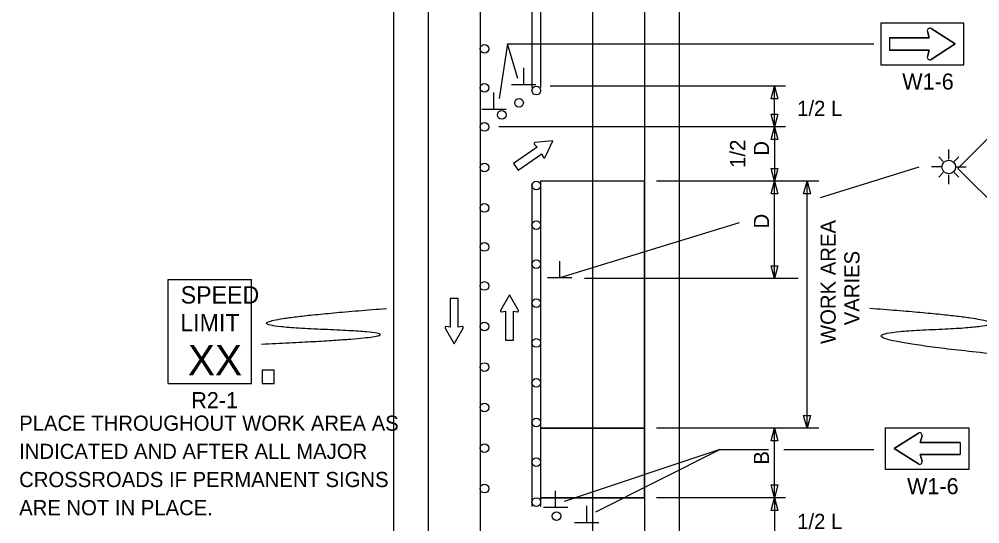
# Model space of a CAD drawing. Extents: x 16731 to 18475, y 7218 to 8213.
# Drawn here: x 16732.4 to 17176, y 7711.7 to 7944.5 of the extents above; entities that cross this region are included whole.
import ezdxf

# ---------------------------------------------------------------- set-up
doc = ezdxf.new("R2010")
doc.units = 0
for name, color, linetype in [('ALI_LEGAL_EX', 7, 'Continuous'), ('MT_SCRATCH_LEVEL_A', 7, 'Continuous'), ('MT_SCRATCH_LEVEL_E', 7, 'Continuous'), ('PAVT_EDGE_EX', 7, 'Continuous'), ('TRAFFIC_SIGNS_PR', 7, 'Continuous'), ('TYPICAL_TEXT_DIMEN_PR', 7, 'Continuous')]:
    doc.layers.add(name, color=color, linetype=linetype)

msp = doc.modelspace()

# ---------------------------------------------------------------- linework, layer by layer
at = {"layer": 'ALI_LEGAL_EX'}
for p, q in [((16945.19, 8201.12), (16945.19, 7350.01)), ((16997.19, 8201.12), (16997.19, 7350.01))]:
    msp.add_line(p, q, dxfattribs=at)
for points in [[(16945.19, 7901.12), (16945.19, 7876.12)], [(16997.19, 7891.94), (16997.19, 7876.12)], [(16945.19, 7801.12), (16945.19, 7776.12)], [(16997.19, 7801.12), (16997.19, 7776.12)]]:
    msp.add_lwpolyline(points, dxfattribs=at)
at = {"layer": 'MT_SCRATCH_LEVEL_A'}
for p, q in [((17021.19, 7869.79), (16973.19, 7869.79)), ((17021.19, 7869.79), (16973.19, 7869.79)), ((16973.19, 7869.79), (16973.19, 7755.78)), ((16973.19, 7869.11), (16973.19, 7723.73)), ((17021.19, 7755.78), (17021.19, 7869.79)), ((17021.19, 7833.79), (17021.19, 7723.73)), ((17021.19, 7755.78), (16973.19, 7755.78)), ((16973.19, 7755.78), (17021.19, 7755.78)), ((17021.19, 7755.78), (16973.19, 7755.78)), ((16973.19, 7755.78), (16973.19, 7723.73)), ((17021.19, 7723.73), (17021.19, 7755.78)), ((17021.19, 7723.73), (16973.19, 7723.73)), ((16973.19, 7723.73), (17021.19, 7723.73))]:
    msp.add_line(p, q, dxfattribs=at)
at = {"layer": 'MT_SCRATCH_LEVEL_E'}
for p, q in [((16970.25, 7886.78), (16971.52, 7885.5)), ((16970.25, 7886.78), (16971.52, 7885.5)), ((16978.82, 7888.34), (16970.53, 7887.57)), ((16978.82, 7888.34), (16970.53, 7887.57)), ((16975.26, 7880.8), (16978.82, 7888.34)), ((16975.26, 7880.8), (16978.82, 7888.34)), ((16971.52, 7885.5), (16960.65, 7877.91)), ((16971.52, 7885.5), (16960.65, 7877.91)), ((16962.8, 7874.85), (16973.67, 7882.44)), ((16962.8, 7874.85), (16973.67, 7882.44)), ((16973.67, 7882.44), (16974.42, 7880.8)), ((16973.67, 7882.44), (16974.42, 7880.8)), ((16960.65, 7877.91), (16962.8, 7874.85)), ((16960.65, 7877.91), (16962.8, 7874.85)), ((16958.8, 7817.35), (16954.69, 7810.11)), ((16958.8, 7817.35), (16954.69, 7810.11)), ((16962.95, 7810.11), (16958.8, 7817.35)), ((16962.95, 7810.11), (16958.8, 7817.35)), ((16935.11, 7815.63), (16931.37, 7815.63)), ((16931.37, 7815.63), (16931.37, 7802.38)), ((16935.11, 7815.63), (16931.37, 7815.63)), ((16931.37, 7815.63), (16931.37, 7802.38)), ((16935.11, 7802.38), (16935.11, 7815.63)), ((16935.11, 7802.38), (16935.11, 7815.63)), ((16955.17, 7809.42), (16956.95, 7809.74)), ((16955.17, 7809.42), (16956.95, 7809.74)), ((16956.95, 7809.74), (16956.95, 7796.48)), ((16956.95, 7809.74), (16956.95, 7796.48)), ((16960.69, 7796.48), (16960.69, 7809.74)), ((16960.69, 7809.74), (16962.47, 7809.42)), ((16960.69, 7796.48), (16960.69, 7809.74)), ((16960.69, 7809.74), (16962.47, 7809.42)), ((16931.37, 7802.38), (16929.59, 7802.69)), ((16931.37, 7802.38), (16929.59, 7802.69)), ((16936.89, 7802.69), (16935.11, 7802.38)), ((16936.89, 7802.69), (16935.11, 7802.38)), ((16929.11, 7802.01), (16933.26, 7794.77)), ((16929.11, 7802.01), (16933.26, 7794.77)), ((16933.26, 7794.77), (16937.37, 7802.01)), ((16933.26, 7794.77), (16937.37, 7802.01)), ((16956.95, 7796.48), (16960.69, 7796.48)), ((16956.95, 7796.48), (16960.69, 7796.48))]:
    msp.add_line(p, q, dxfattribs=at)
for centre, start, end in [((16970.58, 7887.1), 95.3561, 224.8951), ((16970.58, 7887.1), 95.3561, 224.8951), ((16974.84, 7881), 204.9674, 334.7044), ((16974.84, 7881), 204.9674, 334.7044), ((16955.1, 7809.88), 150.4248, 279.9638), ((16955.1, 7809.88), 150.4248, 279.9638), ((16962.54, 7809.88), 260.0362, 29.7731), ((16962.54, 7809.88), 260.0362, 29.7731), ((16929.52, 7802.23), 80.0362, 209.7731), ((16929.52, 7802.23), 80.0362, 209.7731), ((16936.96, 7802.23), 330.4248, 99.9638), ((16936.96, 7802.23), 330.4248, 99.9638)]:
    msp.add_arc(centre, 0.463, start, end, dxfattribs=at)
at = {"layer": 'PAVT_EDGE_EX'}
for p, q in [((16905.19, 8201.12), (16905.19, 7350.01)), ((16921.19, 8201.12), (16921.19, 7350.01)), ((16969.19, 8201.12), (16969.19, 7912.67)), ((16973.19, 8201.12), (16973.19, 7913.05)), ((17021.19, 8201.12), (17021.19, 7350.01)), ((17037.19, 8201.12), (17037.19, 7350.01)), ((16969.19, 7868.73), (16969.19, 7719.73)), ((16973.19, 7833.79), (16973.19, 7719.73))]:
    msp.add_line(p, q, dxfattribs=at)
at = {"layer": 'TRAFFIC_SIGNS_PR'}
for p, q in [((17153.47, 7940.17), (17164.62, 7933.07)), ((17134.22, 7935.87), (17152.62, 7935.87)), ((17134.22, 7935.87), (17134.22, 7930.27)), ((17152.62, 7935.87), (17151.78, 7938.93)), ((17164.62, 7933.07), (17153.47, 7925.96)), ((17152.62, 7930.27), (17134.22, 7930.27)), ((17151.78, 7927.21), (17152.62, 7930.27)), ((17192.97, 7902.81), (17165.82, 7875.65)), ((17161.65, 7879.87), (17161.65, 7884.37)), ((17159.13, 7878.83), (17157.02, 7880.93)), ((17164.16, 7878.83), (17166.27, 7880.93)), ((17158.49, 7876.31), (17153.65, 7876.31)), ((17159.13, 7873.8), (17157.02, 7871.69)), ((17164.16, 7873.8), (17166.27, 7871.69)), ((17164.8, 7876.31), (17169.68, 7876.31)), ((17165.82, 7875.65), (17192.97, 7848.5)), ((17161.65, 7868.35), (17161.65, 7872.76)), ((16801.19, 7824.44), (16839.59, 7824.44)), ((16801.19, 7776.44), (16801.19, 7824.44)), ((16839.59, 7776.44), (16839.59, 7824.44)), ((16801.19, 7776.44), (16839.59, 7776.44)), ((17147.61, 7753.48), (17136.45, 7746.38)), ((17148.45, 7749.18), (17149.29, 7752.24)), ((17166.85, 7749.18), (17148.45, 7749.18)), ((17166.85, 7749.18), (17166.85, 7743.58)), ((17136.45, 7746.38), (17147.61, 7739.28)), ((17149.29, 7740.52), (17148.45, 7743.58)), ((17148.45, 7743.58), (17166.85, 7743.58))]:
    msp.add_line(p, q, dxfattribs=at)
for points in [[(17130.22, 7923.47), (17168.62, 7923.47), (17168.62, 7942.67), (17130.22, 7942.67)], [(16844.61, 7776.44), (16850.2, 7776.44), (16850.2, 7782.62), (16844.61, 7782.62)], [(17170.85, 7736.78), (17132.45, 7736.78), (17132.45, 7755.98), (17170.85, 7755.98)]]:
    msp.add_lwpolyline(points, close=True, dxfattribs=at)
for points in [[(17153.47, 7925.96), (17164.62, 7933.07), (17153.47, 7940.17)], [(17151.78, 7938.93), (17152.62, 7935.87), (17134.22, 7935.87), (17134.22, 7930.27), (17152.62, 7930.27), (17151.78, 7927.21)], [(17147.61, 7739.28), (17136.45, 7746.38), (17147.61, 7753.48)], [(17149.29, 7752.24), (17148.45, 7749.18), (17166.85, 7749.18), (17166.85, 7743.58), (17148.45, 7743.58), (17149.29, 7740.52)]]:
    msp.add_lwpolyline(points, dxfattribs=at)
for centre, radius in [((16947.19, 7930.79), 2), ((16947.2, 7930.79), 2), ((16947.19, 7912.79), 2), ((16971.19, 7911.55), 2), ((16963.19, 7905.96), 2), ((16955.19, 7900.38), 2), ((16947.19, 7894.79), 2), ((16947.19, 7894.79), 2), ((16947.19, 7894.79), 2), ((16947.19, 7876.09), 2), ((17161.65, 7876.31), 3.15), ((16971.19, 7867.79), 2), ((16947.19, 7857.4), 2), ((16971.19, 7849.44), 2), ((16947.19, 7839.4), 2), ((16971.19, 7831.44), 2), ((16947.19, 7821.4), 2), ((16971.19, 7813.44), 2), ((16947.19, 7802.7), 2), ((16971.19, 7795.1), 2), ((16947.19, 7784), 2), ((16971.19, 7776.76), 2), ((16947.19, 7765.3), 2), ((16971.19, 7758.41), 2), ((16947.19, 7746.61), 2), ((16971.19, 7740.07), 2), ((16947.19, 7727.91), 2), ((16971.19, 7721.73), 2), ((16980.53, 7715.2), 2)]:
    msp.add_circle(centre, radius, dxfattribs=at)
for centre, start, end in [((17152.86, 7939.22), 57.5304, 195.3269), ((17152.86, 7939.22), 57.5304, 195.3269), ((17152.86, 7926.91), 164.6731, 302.4696), ((17152.86, 7926.91), 164.6731, 302.4696), ((17148.21, 7752.54), 344.6731, 122.4696), ((17148.21, 7752.54), 344.6731, 122.4696), ((17148.21, 7740.22), 237.5304, 15.3269), ((17148.21, 7740.22), 237.5304, 15.3269)]:
    msp.add_arc(centre, 1.12, start, end, dxfattribs=at)
for points in [[(16844.27, 7794.61), (16937.2, 7798.74), (16808.49, 7803.94), (16902.03, 7811.03)], [(17198.45, 7788.41), (17090.03, 7798.74), (17218.74, 7803.94), (17125.21, 7811.03)]]:
    msp.add_open_spline(points, degree=2, dxfattribs=at)
at = {"layer": 'TYPICAL_TEXT_DIMEN_PR'}
for p, q in [((16957.92, 7933.19), (16954.05, 7907.92)), ((16957.92, 7933.19), (17127.03, 7933.19)), ((16962.66, 7917.2), (16957.92, 7933.19)), ((16965.37, 7914.25), (16965.37, 7922.03)), ((16970.99, 7914.25), (16959.74, 7914.25)), ((17086.19, 7913.55), (16977.61, 7913.55)), ((17079.62, 7907.69), (17081.19, 7913.55)), ((17081.19, 7894.79), (17081.19, 7913.55)), ((17081.19, 7913.55), (17082.76, 7907.69)), ((16951.61, 7902.89), (16951.61, 7910.67)), ((17081.19, 7907.69), (17079.62, 7907.69)), ((17082.76, 7907.69), (17081.19, 7907.69)), ((16957.23, 7902.89), (16945.98, 7902.89)), ((17081.19, 7894.79), (17079.62, 7900.65)), ((17079.62, 7900.65), (17081.19, 7900.65)), ((17081.19, 7900.65), (17082.76, 7900.65)), ((17082.76, 7900.65), (17081.19, 7894.79)), ((17086.19, 7894.79), (16953.88, 7894.79)), ((17079.62, 7888.93), (17081.19, 7894.79)), ((17081.19, 7894.79), (17082.76, 7888.93)), ((17081.19, 7894.79), (17081.19, 7869.79)), ((17081.19, 7888.93), (17079.62, 7888.93)), ((17082.76, 7888.93), (17081.19, 7888.93)), ((17081.19, 7869.79), (17079.62, 7875.65)), ((17079.62, 7875.65), (17081.19, 7875.65)), ((17081.19, 7875.65), (17082.76, 7875.65)), ((17082.76, 7875.65), (17081.19, 7869.79)), ((17147.85, 7876.18), (17102.29, 7862.14)), ((17101.62, 7869.79), (17026.7, 7869.79)), ((17079.62, 7863.93), (17081.19, 7869.79)), ((17081.19, 7824.79), (17081.19, 7869.79)), ((17081.19, 7869.79), (17082.76, 7863.93)), ((17094.62, 7863.93), (17096.19, 7869.79)), ((17096.19, 7755.78), (17096.19, 7869.79)), ((17096.19, 7869.79), (17097.76, 7863.93)), ((17081.19, 7863.93), (17079.62, 7863.93)), ((17082.76, 7863.93), (17081.19, 7863.93)), ((17096.19, 7863.93), (17094.62, 7863.93)), ((17097.76, 7863.93), (17096.19, 7863.93)), ((17064.85, 7850.61), (16982.04, 7825.09)), ((16982.04, 7825.09), (16982.04, 7832.87)), ((17081.19, 7824.79), (17079.62, 7830.65)), ((17079.62, 7830.65), (17081.19, 7830.65)), ((17081.19, 7830.65), (17082.76, 7830.65)), ((17082.76, 7830.65), (17081.19, 7824.79)), ((16987.66, 7825.09), (16976.41, 7825.09)), ((17092.04, 7824.79), (16993.51, 7824.79)), ((17096.19, 7755.78), (17094.62, 7761.65)), ((17094.62, 7761.65), (17096.19, 7761.65)), ((17096.19, 7761.65), (17097.76, 7761.65)), ((17097.76, 7761.65), (17096.19, 7755.78)), ((17101.62, 7755.78), (17026.7, 7755.78)), ((17079.62, 7749.92), (17081.19, 7755.78)), ((17081.19, 7723.73), (17081.19, 7755.78)), ((17081.19, 7755.78), (17082.76, 7749.92)), ((17081.19, 7749.92), (17079.62, 7749.92)), ((17082.76, 7749.92), (17081.19, 7749.92)), ((17055.89, 7745.89), (16984.02, 7721.97)), ((16998.64, 7717.18), (17055.89, 7745.89)), ((17055.89, 7745.9), (17078.47, 7745.9)), ((17085.47, 7745.9), (17127.03, 7745.9)), ((17081.19, 7723.73), (17079.62, 7729.59)), ((17079.62, 7729.59), (17081.19, 7729.59)), ((17081.19, 7729.59), (17082.76, 7729.59)), ((17082.76, 7729.59), (17081.19, 7723.73)), ((16980.09, 7719.18), (16980.09, 7726.96)), ((17086.19, 7723.73), (17026.7, 7723.73)), ((17079.62, 7717.86), (17081.19, 7723.73)), ((17081.19, 7723.73), (17081.19, 7702.15)), ((17081.19, 7723.73), (17082.76, 7717.86)), ((16985.72, 7719.18), (16974.47, 7719.18)), ((16994.48, 7712.16), (16994.48, 7719.95)), ((17081.19, 7717.86), (17079.62, 7717.86)), ((17082.76, 7717.86), (17081.19, 7717.86)), ((17000.1, 7712.16), (16988.85, 7712.16))]:
    msp.add_line(p, q, dxfattribs=at)

# ---------------------------------------------------------------- texts
at = {"layer": 'TRAFFIC_SIGNS_PR'}
for s, height, p in [('W1-6', 7.44, (17140.16, 7912.03)), ('SPEED', 8, (16806.96, 7813.31)), ('LIMIT', 8, (16806.79, 7800.51)), ('XX', 14.031, (16810.3, 7780.2)), ('R2-1', 7.44, (16811.87, 7765)), ('PLACE THROUGHOUT WORK AREA AS', 7, (16732.38, 7754.61)), ('INDICATED AND AFTER ALL MAJOR', 7, (16732.38, 7741.61)), ('CROSSROADS IF PERMANENT SIGNS', 7, (16732.38, 7728.61)), ('W1-6', 7.44, (17142.39, 7725.34)), ('ARE NOT IN PLACE.', 7, (16732.38, 7715.61))]:
    msp.add_text(s, height=height, dxfattribs=at).set_placement(p)
at = {"layer": 'TYPICAL_TEXT_DIMEN_PR'}
for p in [(17091.66, 7899.88), (17091.66, 7709.28)]:
    msp.add_text('1/2 L', height=7, dxfattribs=at).set_placement(p)
for s, p in [('1/2', (17067.63, 7875.94)), ('D', (17078.63, 7881.51)), ('D', (17078.63, 7847.95)), ('WORK AREA', (17109.42, 7794.63)), ('VARIES', (17120.42, 7803.27)), ('B', (17078.63, 7738.99))]:
    msp.add_text(s, height=7, rotation=90, dxfattribs=at).set_placement(p)

doc.saveas('drawing.dxf')
